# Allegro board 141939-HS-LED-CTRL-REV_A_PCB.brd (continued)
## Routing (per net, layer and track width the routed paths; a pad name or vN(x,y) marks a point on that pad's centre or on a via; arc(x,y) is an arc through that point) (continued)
SD_A11: length 34.6
  TOP w0.152: P1.P8 v1(84.91,34.66)
  BOTTOM w0.152: U5.35 106.33,48.33 104.27,50.39 93.6,50.39 88.4,45.18 88.4,44.42 84.91,40.93 v1(84.91,34.66)
SD_BA0: length 30.9
  TOP w0.152: P1.K2 v1(90.91,30.66)
  BOTTOM w0.152: v1(90.91,30.66) 91.15,30.66 91.65,31.16 93.81,31.16 94.16,31.52 94.42,31.52 95.29,30.64 95.54,30.64 95.72,30.82 95.72,31.08 94.85,31.95 94.85,32.2 95.03,32.38 95.28,32.38 96.15,31.51 96.4,31.51 96.58,31.69 96.58,31.94 95.82,32.7 95.82,33.21 97.3,34.69 98.06,34.69 98.24,34.86 98.24,35.12 97.73,35.63 97.73,35.88 97.91,36.06 98.16,36.06 98.67,35.55 98.92,35.55 99.1,35.73 99.1,35.98 98.48,36.6 98.48,36.85 100.62,38.99 105.33,38.99 105.54,38.79 105.54,37.54 105.74,37.34 106.24,37.34 106.33,37.25 U5.20
SD_BA1: length 30.6
  TOP w0.152: P1.K1 v1(91.91,30.66)
  BOTTOM w0.152: v1(91.91,30.66) 94.16,30.66 94.36,30.46 94.36,30.43 94.56,30.23 95.63,30.23 97.03,31.62 97.03,32.13 96.27,32.89 96.27,33.15 96.43,33.31 96.68,33.31 97.57,32.42 97.83,32.42 98,32.6 98,32.85 97.11,33.74 97.11,34 97.29,34.17 97.55,34.17 98.37,33.35 98.62,33.35 98.8,33.53 98.8,33.78 98.44,34.14 98.44,34.43 99.46,35.45 99.75,35.45 99.79,35.4 100.05,35.4 100.22,35.58 100.22,35.83 99.71,36.34 99.71,36.6 100.33,37.21 100.33,38.15 100.53,38.35 101.4,38.35 101.6,38.15 101.6,37.39 101.78,37.21 102.04,37.21 102.21,37.39 102.21,38.27 102.55,38.61 105,38.61 105.16,38.45 105.16,37.38 105.53,37 U5.21
SD_CAS: length 32.1
  TOP w0.152: P1.F2 90.91,25.66 93.77,25.66 94.49,26.39 94.49,28.15 95.68,29.34 97.97,29.34 98.18,29.54 v1(98.18,29.69)
  BOTTOM w0.152: U5.17 108.73,33.99 108.53,33.78 107.47,33.78 107.27,33.99 107.27,34.75 107.09,34.92 106.84,34.92 106.66,34.75 106.66,33.96 106.48,33.78 103.84,33.78 103.64,33.58 103.64,29.82 103.5,29.69 100.29,29.69 100.11,29.51 100.11,28.25 99.93,28.07 99.68,28.07 99.5,28.25 99.5,29.51 99.32,29.69 v1(98.18,29.69)
SD_CKE: length 32.8
  TOP w0.152: P1.M6 v1(86.91,32.66)
  BOTTOM w0.152: U5.37 107.93,45.83 107.18,45.08 93.5,45.08 92.79,44.37 92.79,41.36 89.53,38.1 89.53,35.15 89.41,35.03 89.41,34.87 89.41,34.87 89.41,34.51 89.41,34.51 89.41,34.46 89.12,34.16 89.06,34.16 89.06,34.16 88.7,34.16 88.41,33.87 88.41,33.51 88.41,33.51 88.41,33.46 88.12,33.16 87.41,33.16 v1(86.91,32.66)
SD_CLK: length 30.3
  TOP w0.152: P1.T4 88.41,37.74 v4(89.03,38.35) 93.35,42.68 v1(93.35,44.04)
  BOTTOM w0.152: U5.38 108.73,46.15 108.91,45.97 109.93,45.97 110.11,45.79 110.11,45.54 109.93,45.36 108.91,45.36 108.73,45.18 108.73,45.11 108.35,44.72 94.03,44.72 v1(93.35,44.04)
SD_CS: length 30.3
  TOP w0.152: P1.L1 v1(91.91,31.66)
  BOTTOM w0.152: U5.19 107.13,37.03 107.3,37.2 107.41,37.2 107.57,37.36 107.57,37.59 107.41,37.75 106.1,37.75 105.92,37.92 105.92,38.18 106.1,38.35 107.26,38.35 107.44,38.53 107.44,38.79 107.26,38.96 105.99,38.96 105.59,39.37 100.36,39.37 97.06,36.06 97.06,35.81 97.36,35.51 97.36,35.26 97.18,35.08 96.93,35.08 96.63,35.38 96.37,35.38 96.19,35.2 96.19,34.95 96.5,34.65 96.5,34.39 96.32,34.21 96.06,34.21 95.76,34.52 95.51,34.52 95.25,34.26 95.25,34.02 95.26,34.02 95.59,33.7 95.59,33.48 95.39,33.29 95.14,33.29 94.95,33.48 94.7,33.48 94.52,33.3 94.52,33.05 94.71,32.86 94.71,32.61 94.53,32.43 94.28,32.43 94.09,32.62 93.83,32.62 93.65,32.44 93.65,32.19 93.85,32 93.85,31.74 93.77,31.66 v1(91.91,31.66)
SD_D0: length 43.4
  TOP w0.152: P1.P3 v1(89.91,34.66)
  BOTTOM w0.152: U5.2 120.73,40.56 117,44.29 109.19,44.29 108.33,43.43 95.54,43.43 89.91,37.81 v1(89.91,34.66)
SD_D1: length 41.9
  TOP w0.152: P1.N3 v1(89.91,33.66)
  BOTTOM w0.152: v1(89.91,33.66) 89.91,33.92 90.41,34.42 90.41,36.43 v3(90.55,36.58) 90.55,37.68 95.92,43.05 110.14,43.05 110.79,43.7 116.07,43.7 119.13,40.64 U5.4
SD_D2: length 41.4
  TOP w0.152: P1.P2 v1(90.91,34.66)
  BOTTOM w0.152: v1(90.91,34.66) 90.91,34.74 93.6,37.43 93.6,38.86 93.09,39.37 93.09,39.62 93.49,40.02 93.74,40.02 93.93,39.83 94.18,39.83 94.36,40.01 94.36,40.26 94.17,40.45 94.17,40.7 94.35,40.88 94.6,40.88 94.79,40.69 95.05,40.69 95.22,40.87 95.22,41.12 95.03,41.31 95.03,41.57 95.21,41.74 95.46,41.74 95.66,41.55 95.91,41.55 96.09,41.73 96.09,41.98 95.89,42.18 95.89,42.43 96.04,42.57 116.43,42.57 118.33,40.67 U5.5
SD_D3: length 42.4
  TOP w0.152: P1.L6 v1(86.91,31.66)
  BOTTOM w0.152: v1(86.91,31.66) 88.27,31.66 88.41,31.81 88.41,32.87 88.7,33.16 90.12,33.16 90.41,33.46 90.41,33.87 90.7,34.16 91.12,34.16 91.57,34.62 91.57,34.77 93.98,37.18 93.98,39.12 97.08,42.21 115.52,42.21 116.73,41 U5.7
SD_D4: length 41.2
  TOP w0.152: P1.N2 v1(90.91,33.66)
  BOTTOM w0.152: U5.8 115.93,41.17 115.24,41.86 97.23,41.86 96.78,41.41 96.78,41.16 97.29,40.65 97.29,40.4 97.12,40.22 96.86,40.22 96.35,40.73 96.1,40.73 95.92,40.55 95.92,40.3 96.43,39.79 96.43,39.54 96.25,39.36 96,39.36 95.49,39.87 95.24,39.87 95.06,39.69 95.06,39.44 95.57,38.93 95.57,38.67 95.39,38.49 95.14,38.49 94.63,39 94.49,39 94.36,38.88 94.36,37.94 94.72,37.58 94.72,37.28 91.1,33.66 v1(90.91,33.66)
SD_D5: length 41.4
  TOP w0.152: P1.L4 v1(88.91,31.66)
  BOTTOM w0.152: v1(88.91,31.66) 89.41,32.16 90.19,32.16 92.22,34.2 92.22,34.27 95.12,37.18 95.12,37.72 98.04,40.64 98.04,40.77 97.79,41.02 97.79,41.38 97.92,41.5 112.7,41.5 112.88,41.33 112.88,40.82 113.06,40.64 113.31,40.64 113.49,40.82 113.49,41.33 113.67,41.5 113.92,41.5 114.1,41.33 114.1,40.82 114.28,40.64 114.53,40.64 114.71,40.82 114.71,41.33 114.89,41.5 115.09,41.5 115.57,41.02 115.57,37.34 115.44,37.21 114.55,37.21 114.33,36.99 U5.10
SD_D6: length 42.2
  TOP w0.152: P1.L3 v1(89.91,31.66)
  BOTTOM w0.152: v1(89.91,31.66) 90.12,31.66 91.45,32.99 91.7,32.99 91.88,32.82 92.13,32.82 92.31,33 92.31,33.25 92.13,33.43 92.13,33.68 95.58,37.13 95.58,37.67 99.06,41.15 110.26,41.15 110.62,40.79 110.62,40.46 110.82,40.26 111.61,40.26 111.82,40.46 111.82,40.97 112,41.15 112.25,41.15 112.43,40.97 112.43,40.44 112.61,40.26 115.04,40.26 115.19,40.11 115.19,39.9 115.04,39.75 114.23,39.75 114.05,39.57 114.05,39.3 114.23,39.12 115.04,39.12 115.19,38.97 115.19,38.76 115.04,38.61 114.19,38.61 114.05,38.46 114.05,38.25 114.19,38.1 115.04,38.1 115.19,37.95 115.19,37.74 115.04,37.59 114.17,37.59 113.98,37.4 113.98,37.15 113.92,37.08 113.67,37.08 113.53,36.95 U5.11
SD_D7: length 41.3
  TOP w0.152: P1.N1 91.91,33.66 v1(92.91,33.66)
  BOTTOM w0.152: U5.13 111.93,37.01 112.14,37.21 113.26,37.21 113.41,37.36 113.41,37.57 113.26,37.72 111.53,37.72 111.38,37.87 111.38,38.08 111.53,38.23 113.52,38.23 113.67,38.38 113.67,38.59 113.52,38.73 111.42,38.73 111.25,38.91 111.25,39.15 111.42,39.32 113.5,39.32 113.67,39.48 113.67,39.71 113.5,39.88 110.44,39.88 110.24,40.08 110.24,40.61 110.08,40.77 109.87,40.77 109.72,40.61 109.72,40.02 109.57,39.88 109.37,39.88 109.22,40.02 109.22,40.41 108.86,40.77 99.19,40.77 96.01,37.59 96.01,37.05 92.91,33.95 v1(92.91,33.66)
SD_D8: length 67.9
  TOP w0.152: P1.M8 v1(84.91,32.66)
  BOTTOM w0.152: v1(84.91,32.66) 84.91,32.67 84.08,33.5 84.08,41.75 84.71,42.39 84.71,49.03 85.37,49.68 85.62,49.68 86.19,49.11 86.45,49.11 86.62,49.29 86.62,49.54 86.05,50.11 86.05,50.36 86.23,50.54 86.48,50.54 87.06,49.97 87.31,49.97 87.49,50.15 87.49,50.4 86.91,50.97 86.91,51.23 87.35,51.66 108.71,51.66 108.89,51.84 108.89,53.54 109.07,53.72 109.32,53.72 109.5,53.54 109.5,52.38 109.68,52.2 109.93,52.2 110.11,52.38 110.11,53.54 110.29,53.72 111.18,53.72 111.38,53.52 111.38,53.16 111.2,52.98 110.67,52.98 110.49,52.8 110.49,52.55 110.67,52.37 111.2,52.37 111.38,52.19 111.38,51.94 111.2,51.76 110.16,51.76 109.98,51.58 109.98,51.33 110.16,51.15 111.96,51.15 112.14,50.97 112.14,50.72 111.96,50.54 110.16,50.54 109.98,50.36 109.98,50.11 110.16,49.93 111.2,49.93 111.38,49.75 111.38,49.25 111.93,48.7 U5.42
SD_D9: length 68.3
  TOP w0.152: P1.L8 v1(84.91,31.66)
  BOTTOM w0.152: U5.44 113.53,48.22 114.18,48.86 114.18,49.84 111.89,52.13 111.89,53.9 111.68,54.1 108.7,54.1 108.52,53.92 108.52,52.38 108.34,52.2 108.09,52.2 107.91,52.38 107.91,53.92 107.73,54.1 107.48,54.1 107.3,53.92 107.3,52.38 107.12,52.2 106.87,52.2 106.69,52.38 106.69,53.92 106.51,54.1 106.26,54.1 106.08,53.92 106.08,52.38 105.9,52.2 105.65,52.2 105.47,52.38 105.47,54.06 105.31,54.23 105.07,54.23 104.9,54.06 104.9,52.24 104.7,52.04 86.84,52.04 83.42,48.62 83.42,36.19 83.77,35.83 83.77,32.8 v1(84.91,31.66)
SD_D10: length 67.6
  TOP w0.152: P1.L9 83.41,31.16 v1(82.91,31.66)
  BOTTOM w0.152: v1(82.91,31.66) 83.44,32.2 83.44,35.53 83.06,35.91 83.06,49.03 86.46,52.42 104.11,52.42 104.52,52.83 104.52,54.23 104.9,54.61 108.38,54.61 108.58,54.81 108.58,56.31 108.79,56.52 109.02,56.52 109.22,56.31 109.22,54.81 109.42,54.61 109.65,54.61 109.86,54.81 109.86,56.31 110.06,56.52 110.29,56.52 110.49,56.31 110.49,54.64 110.65,54.48 110.88,54.48 111.04,54.64 111.04,55.45 111.22,55.63 111.47,55.63 111.65,55.45 111.65,54.79 111.83,54.61 112.06,54.61 112.27,54.41 112.27,52.55 114.56,50.26 114.56,48.48 114.33,48.26 U5.45
SD_D11: length 68.1
  TOP w0.152: P1.N9 83.41,33.16 v1(82.91,33.66)
  BOTTOM w0.152: v1(82.91,33.66) 82.91,35.3 82.68,35.53 82.68,49.53 85.95,52.8 103.81,52.8 104.01,53 104.01,54.79 104.22,54.99 105.46,54.99 105.66,55.19 105.66,56.69 105.87,56.9 106.1,56.9 106.3,56.69 106.3,55.19 106.5,54.99 106.73,54.99 106.93,55.19 106.93,56.69 107.14,56.9 107.37,56.9 107.57,56.69 107.57,55.19 107.77,54.99 108,54.99 108.2,55.19 108.2,56.69 108.41,56.9 110.74,56.9 112.78,54.86 112.78,52.81 115.19,50.39 115.19,49.22 115.93,48.48 U5.47
SD_D12: length 68.1
  TOP w0.152: v1(82.91,32.66) 83.41,32.16 P1.M9
  BOTTOM w0.152: v1(82.91,32.66) 82.41,33.16 82.41,35.17 82.3,35.28 82.3,53.18 84.59,55.47 103.81,55.47 104.01,55.67 104.01,57.07 104.22,57.28 104.44,57.28 104.65,57.07 104.65,55.67 104.85,55.47 105.08,55.47 105.28,55.67 105.28,57.07 105.49,57.28 110.87,57.28 115.83,52.32 115.83,49.19 116.73,48.29 U5.48
SD_D13: length 69.4
  TOP w0.152: v1(81.91,31.66) 82.41,31.16 P1.L10
  BOTTOM w0.152: U5.50 118.33,50.42 110.89,57.86 84.66,57.86 81.06,54.26 81.06,43.3 80.14,42.39 80.14,37.56 81.16,36.55 81.16,35.15 81.41,34.9 81.41,32.16 v1(81.91,31.66)
SD_D14: length 67.9
  TOP w0.152: v1(80.91,34.66) 81.41,34.16 P1.P11
  BOTTOM w0.152: v1(80.91,34.66) 80.78,34.8 80.78,36.16 79.63,37.31 79.63,43.02 80.4,43.79 80.4,54.33 84.37,58.29 111.23,58.29 119.13,50.39 U5.51
SD_D15: length 68.1
  TOP w0.152: P1.T14 78.41,36.16 v1(77.91,36.66)
  BOTTOM w0.152: U5.53 120.73,49.42 111.48,58.67 83.63,58.67 79.93,54.97 79.93,43.99 77.98,42.04 77.98,36.74 v1(77.91,36.66)
SD_DQ0: length 41.3
  TOP w0.152: P1.L2 v1(90.91,31.66)
  BOTTOM w0.152: U5.15 110.33,36.98 110.54,37.19 111.13,37.19 111.25,37.3 111.25,37.47 111.13,37.59 109.59,37.59 109.47,37.7 109.47,37.86 109.59,37.97 110.85,37.97 111,38.12 111,38.33 110.85,38.48 108.48,38.48 108.33,38.63 108.33,38.84 108.48,38.99 110.72,38.99 110.87,39.14 110.87,39.35 110.72,39.5 109.04,39.5 108.84,39.7 108.84,40.03 108.64,40.23 107.72,40.23 107.55,40.05 107.55,39.93 107.37,39.75 107.11,39.75 106.94,39.93 106.94,40.18 106.73,40.39 100.13,40.39 99.86,40.11 99.68,40.11 99.59,40.2 99.33,40.2 99.15,40.02 99.15,39.77 99.24,39.68 99.24,39.43 99.07,39.25 98.81,39.25 98.62,39.44 98.37,39.44 98.19,39.26 98.19,39.01 98.38,38.82 98.38,38.56 98.2,38.39 97.95,38.39 97.76,38.58 97.51,38.58 97.33,38.4 97.33,38.15 97.52,37.95 97.52,37.7 97.34,37.52 97.09,37.52 96.9,37.72 96.64,37.72 96.46,37.54 96.46,37.39 96.65,37.21 96.65,37.08 94.29,34.73 94.29,34.48 94.36,34.41 94.36,34.16 94.18,33.98 93.93,33.98 93.86,34.05 93.64,34.05 93.5,33.91 93.5,33.66 93.6,33.56 93.6,33.49 92.62,32.51 91.6,32.51 90.91,31.82 v1(90.91,31.66)
SD_DQ1: length 68.9
  TOP w0.152: P1.N8 v1(84.91,33.66)
  BOTTOM w0.152: U5.39 109.53,50.95 109.33,51.15 109,51.15 108.82,50.97 108.82,49.71 108.64,49.53 108.39,49.53 108.21,49.71 108.21,50.97 108.03,51.15 107.78,51.15 107.6,50.97 107.6,49.71 107.42,49.53 107.17,49.53 106.99,49.71 106.99,50.97 106.81,51.15 106.56,51.15 106.38,50.97 106.38,49.71 106.2,49.53 105.95,49.53 105.77,49.71 105.77,50.97 105.59,51.15 91.83,51.15 91.66,50.97 91.66,49.07 91.48,48.9 91.22,48.9 91.05,49.07 91.05,50.97 90.87,51.15 90.61,51.15 90.44,50.97 90.44,48.31 90.26,48.13 90.01,48.13 89.83,48.31 89.83,50.97 89.65,51.15 89.4,51.15 89.22,50.97 89.22,48.31 89.04,48.13 88.79,48.13 88.61,48.31 88.61,50.97 88.43,51.15 88.09,51.15 87.88,50.95 87.88,47.97 87.71,47.8 87.68,47.8 86.74,46.86 86.74,43.4 84.46,41.12 84.46,34.92 84.41,34.87 84.41,34.16 v1(84.91,33.66)
SD_RAS: length 30.3
  TOP w0.152: P1.K5 v1(87.91,30.66)
  BOTTOM w0.152: U5.18 107.93,37.29 108.14,37.5 108.91,37.5 109.09,37.67 109.09,37.93 108.91,38.1 108.11,38.1 107.93,38.28 107.93,39.01 107.57,39.37 106.17,39.37 105.79,39.75 100.08,39.75 94.87,34.54 94.87,34.16 92.87,32.16 91.7,32.16 91.41,31.87 91.41,31.56 91.41,31.46 91.12,31.16 88.11,31.16 87.91,30.96 v1(87.91,30.66)
SD_WE: length 31.4
  TOP w0.152: P1.D1 93.14,24.16 93.32,23.98 93.32,23.17 93.49,22.99 93.75,22.99 93.93,23.17 93.93,23.98 94.1,24.16 94.33,24.16 94.49,24 94.49,23.24 94.61,23.11 94.77,23.11 95.12,23.46 98.94,23.46 100.08,24.61 100.08,28.42 v1(100.72,29.05)
  BOTTOM w0.152: U5.16 109.53,34.67 109.28,34.42 109.28,33.97 108.71,33.4 105.06,33.4 104.02,32.36 104.02,29.31 103.76,29.05 v1(100.72,29.05)
SWCLK: length 19.8
  TOP w0.152: U26.76 119.1,15.69 120.97,17.56 120.97,20.48 122.56,22.07 122.56,28.67 122.94,29.05 R129.2 123.35,29.02 J3.2
SWDIO: length 25.9
  TOP w0.152: v1(119,16.48) 120.53,18 120.53,20.8 122.18,22.45 122.18,30.07 122.81,30.7 R130.1 125.48,30.7 J3.3 ; U26.72 v1(113.85,15.26)
  BOTTOM w0.152: v1(113.85,15.26) 115.07,16.48 v1(119,16.48)
TCK: length 46.7
  TOP w0.152: P1.H3 v1(89.91,28.66)
  BOTTOM w0.152: v1(89.91,28.66) 92.33,28.66 92.58,28.41 92.58,25.88 95.13,23.34 101.44,23.34 104.65,26.54 109.73,26.54 110.39,25.88 121.67,25.88 R11.2 122.31,24.86 122.56,24.61 123.19,24.61 123.83,23.97 123.83,21.94 123.39,21.5 U6.1 122.71,20.4 J1.1
TDI: length 54.9
  TOP w0.152: v1(92.08,27.66) 88.92,27.66 P1.H4
  BOTTOM w0.152: J1.9 120.65,14.46 120.65,22.07 121.99,23.4 U6.3 122.71,23.95 122.56,24.1 122.31,24.1 121.29,25.12 110.27,25.12 109.22,26.16 104.78,26.16 101.57,22.96 94.75,22.96 92.08,25.62 v1(92.08,27.66)
TDO: length 53.9
  TOP w0.152: P1.J4 v1(88.91,28.66)
  BOTTOM w0.152: J1.3 123.67,17.46 124.62,18.41 124.62,20.08 125.21,20.67 U6.6 124.4,21.5 124.21,21.69 124.21,25.24 123.96,25.5 123.96,27.15 122.18,28.93 111.26,28.93 109.38,27.05 104.65,27.05 101.32,23.72 95.51,23.72 92.96,26.26 92.96,28.55 92.21,29.31 89.79,29.31 89.15,28.66 v1(88.91,28.66)
TF_CLK: length 32.7
  TOP w0.152: U26.80 118.05,17.69 118.37,18 118.37,21.31 120.4,23.34 120.4,29.18 117.48,32.1 117.48,35.02 115.32,37.18 115.32,40.36 113.64,42.04 J4.5 111.29,42.04 111.13,41.88 R163.2
TF_CMD: length 39.6
  TOP w0.152: U26.83 115.36,19.19 v1(115.19,19.02) ; R162.2 R139.2 110.19,44.24 J4.3 113.85,44.24 116.08,42.01 116.08,37.05 117.86,35.28 117.86,32.43 120.86,29.43 120.86,23.16 119,21.31 v1(119,19.02)
  BOTTOM w0.152: v1(115.19,19.02) v1(119,19.02)
TF_DATA0: length 39.2
  TOP w0.152: v1(118.75,22.58) 119.89,23.72 119.89,29.05 116.97,31.97 116.97,34.89 114.81,37.05 114.81,38.58 113.55,39.84 J4.7 111.38,39.84 111.13,39.59 R138.2 R158.2 ; U26.65 110.35,15.65 111.68,16.98 v1(114.18,16.98)
  BOTTOM w0.152: v1(114.18,16.98) 114.18,19.02 117.73,22.58 v1(118.75,22.58)
TF_DATA1: length 36.5
  TOP w0.152: U26.66 110.85,14.93 112.02,16.1 v1(113.16,16.1) ; R159.2 R137.2 110.4,38.74 J4.8 113.51,38.74 114.05,38.2 114.05,37.18 116.46,34.77 116.46,31.85 119.51,28.8 119.51,24.61 v1(118.75,23.85)
  BOTTOM w0.152: v1(118.75,23.85) 118.24,23.85 113.16,18.77 v1(113.16,16.1)
TF_DATA2: length 40.9
  TOP w0.152: R160.2 R141.2 111.27,46.44 J4.1 113.68,46.44 119,41.12 119,32.61 121.67,29.94 121.67,22.58 120.12,21.02 120.12,18.48 118.32,16.69 U26.78
TF_DATA3: length 38.4
  TOP w0.152: U26.79 118.19,17.19 119.72,18.72 119.72,21.39 121.29,22.96 121.29,29.69 118.24,32.74 118.24,40.74 113.64,45.34 J4.2 111.03,45.34 111,45.31 R161.2 R140.2
TMS: length 59.2
  TOP w0.152: P1.J5 v1(87.91,29.66)
  BOTTOM w0.152: J1.5 123.65,15.54 124.59,16.48 126.37,16.48 127,17.11 127,22.83 126.44,23.4 U6.4 125.21,24.88 R12.1 124.46,25.62 124.46,28.16 123.32,29.31 110.88,29.31 109.99,28.42 101.73,28.42 99.45,26.13 94.26,26.13 93.73,26.67 93.73,29.08 92.65,30.16 88.41,30.16 v1(87.91,29.66)
USART_RX: length 32.4
  TOP w0.152: U26.26 103.3,27.69 104.27,26.72 104.27,25.65 v1(104.78,25.15)
  BOTTOM w0.152: J7.2 113.45,5.8 110.88,8.38 110.88,15.59 107.7,18.77 107.7,22.6 106.05,24.26 106.05,24.89 105.79,25.15 v1(104.78,25.15)
USART_TO_FPGA_RX: length 43.6
  TOP w0.152: P1.A13 79.41,16.96 84.71,11.65 91.44,11.65 94.75,8.35 107.7,8.35 112.35,13 U26.69
USART_TO_FPGA_TX: length 43.2
  TOP w0.152: P1.B13 79.89,21.68 79.89,19.57 79.89,19.56 79.89,17.12 84.97,12.03 92.21,12.03 95.39,8.85 107.62,8.85 111.85,13.08 U26.68
USART_TX: length 31
  TOP w0.152: v1(105.41,24.48) 105.41,26.59 103.35,28.65 U26.25
  BOTTOM w0.152: v1(105.41,24.48) 105.41,24.1 107.06,22.45 107.06,18.76 109.59,16.23 109.59,7.88 111.45,6.03 J7.1
WR: length 34.2
  TOP w0.152: v1(105.41,19.65) 113.14,19.65 114.18,20.69 U26.86 ; P1.C6 v1(86.91,22.66)
  BOTTOM w0.152: v1(105.41,19.65) 104.86,19.1 103.71,19.1 103.51,18.89 88.9,18.89 86.91,20.89 v1(86.91,22.66)
N00507: length 2.6
  TOP w0.381: U1.7 22.1,49.41 21.21,48.52 R1.1
N00656: length 2.5
  TOP w0.381: U1.8 21.75,48.14 21.12,47.5 C2.1
N00761: length 1
  TOP w0.381: R2.1 C3.2
N00851: length 2.2
  TOP w0.381: U1.6 C3.1
N00855: length 0.7
  TOP w0.381: C4.1 31.28,47.25
N00885: length 3.2
  TOP w0.381: C4.2 30.26,47.31 29.44,48.14 U1.1
N00957: length 5
  TOP w0.381: R4.2 R3.2 24.64,52.55 24.04,51.95 U1.5
N59239: length 3.1
  TOP w0.152: U8.2 48.05,41.16 48.21,41.33
  TOP w0.381: L6.2 49.02,41.84 48.76,41.58 48.47,41.58 48.21,41.33
N59407: length 6.4
  TOP w0.152: Y1.3 45.25,44.5 45.25,44.04 C41.2 46.01,42.51 46.65,42.51 46.84,42.31 U8.5
N59411: length 8.3
  TOP w0.152: Y1.1 45.97,46.92 45.63,46.58 45.63,44.17 C39.2 46.14,43.15 46.39,42.9 46.9,42.9 47.25,42.55 U8.4
N59605: length 4
  TOP w0.152: 48.21,23.8 48.05,23.63 U9.2
  TOP w0.381: 48.21,23.8 48.64,24.23 49.44,24.23 49.91,24.7 L7.2
N59753: length 5.2
  TOP w0.152: Y2.3 46.14,26.47 46.14,26 C42.2 46.39,24.99 46.52,24.99 46.84,24.66 U9.5
N59757: length 7.1
  TOP w0.152: Y2.1 46.86,28.89 46.52,28.54 46.52,26.13 C40.2 47.25,25.4 U9.4
N68560: length 2.3
  TOP w0.381: U23.1 v1(35.34,17.88)
  BOTTOM w0.381: C226.2 v1(35.34,17.88)
N68564: length 2.4
  TOP w0.381: U23.48 v1(21.12,17.88)
  BOTTOM w0.381: R111.1 v1(21.12,17.88)
N68628: length 2.3
  TOP w0.381: U23.4 v1(35.34,20.92)
  BOTTOM w0.381: C227.2 v1(35.34,20.92)
N68632: length 2.4
  TOP w0.381: U23.45 v1(21.12,20.92)
  BOTTOM w0.381: R112.1 v1(21.12,20.92)
N68696: length 2.3
  TOP w0.381: U23.7 v1(35.34,23.97)
  BOTTOM w0.381: v1(35.34,23.97) C228.2
N68700: length 2.4
  TOP w0.381: U23.42 v1(21.12,23.97)
  BOTTOM w0.381: R113.1 v1(21.12,23.97)
N68748: length 2.3
  TOP w0.381: U23.10 v1(35.34,27.02)
  BOTTOM w0.381: C229.2 v1(35.34,27.02)
N68752: length 2.4
  TOP w0.381: U23.39 v1(21.12,27.02)
  BOTTOM w0.381: R114.1 v1(21.12,27.02)
N68848: length 2.3
  TOP w0.381: U23.13 v1(35.34,30.07)
  BOTTOM w0.381: C230.2 v1(35.34,30.07)
N68852: length 2.4
  TOP w0.381: U23.36 v1(21.12,30.07)
  BOTTOM w0.381: R115.1 v1(21.12,30.07)
N68966: length 2.3
  TOP w0.381: U23.16 v1(35.34,33.12)
  BOTTOM w0.381: C231.2 v1(35.34,33.12)
N68970: length 2.4
  TOP w0.381: U23.33 v1(21.12,33.12)
  BOTTOM w0.381: R116.1 v1(21.12,33.12)
N69086: length 2.3
  TOP w0.381: U23.19 v1(35.34,36.16)
  BOTTOM w0.381: C232.2 v1(35.34,36.16)
N69090: length 2.4
  TOP w0.381: U23.30 v1(21.12,36.16)
  BOTTOM w0.381: R117.1 v1(21.12,36.16)
N69194: length 2.3
  TOP w0.381: U23.22 v1(35.34,39.21)
  BOTTOM w0.381: C233.2 v1(35.34,39.21)
N69198: length 2.4
  TOP w0.381: U23.27 v1(21.12,39.21)
  BOTTOM w0.381: R118.1 v1(21.12,39.21)
N70343: length 9.5
  TOP w0.152: v1(78.91,28.66) 79.91,28.66 P1.H12
  BOTTOM w0.152: v1(78.91,28.66) 78.49,29.08 74.55,29.08 74.04,28.57 72.39,28.57 R164.1
N5916714: length 5.7
  TOP w0.152: U8.7 46.05,41.51 45.76,41.8 45.76,42.13 45.38,42.51 44.87,42.51 44.71,42.36 43.88,42.36 R31.1
N5956514: length 5.8
  TOP w0.152: U9.7 46.05,23.99 45.76,24.28 45.76,24.61 45.38,24.99 43.72,24.99 43.09,25.62 R33.1
N15733620: length 21.9
  TOP w0.152: R127.2 v1(116.08,11.91) ; U26.16 107.85,24.58 v1(107.95,24.48)
  BOTTOM w0.152: v1(107.95,24.48) 108.97,23.46 108.97,19.02 v1(116.08,11.91)
N15733628: length 21.9
  TOP w0.152: R128.2 v1(114.43,11.91) ; U26.17 107.35,25.15 v1(106.68,24.48)
  BOTTOM w0.152: v1(114.43,11.91) 114.43,12.8 108.34,18.89 108.34,22.83 v1(106.68,24.48)
N15733972: length 3.7
  TOP w0.152: U26.94 118.19,24.69 118.88,25.37 R131.2
N15734280: length 9.2
  TOP w0.229: v1(104.65,31.85) 105.21,31.29 105.21,30.72 105.35,30.58 U26.21 ; v1(104.65,30.7) 104.85,30.5 U26.22
  BOTTOM w0.381: L10.1 107.61,32.74 C251.2 C252.2 105.16,32.74 104.65,32.23 v1(104.65,31.85) v1(104.65,30.7)
N15734652: length 2.7
  TOP w0.152: R135.2 99.07,22.19 U26.37
N15801432: length 1.5
  BOTTOM w0.305: U25.4 C242.1
N15813450: length 1.3
  TOP w0.381: R142.1 D26.1
N15817579: length 2.3
  TOP w0.152: R13.2 U7.2
N15925802: length 1.4
  TOP w0.152: D37.1 15.24,47.6 R146.2
N15925882: length 1.4
  TOP w0.152: D36.1 12.2,47.6 R147.2
N15925976: length 1.4
  TOP w0.152: R148.2 12.2,11.16 D35.1
N15926055: length 1.4
  TOP w0.152: D34.1 15.63,12.53 R149.2
N15994943: length 3.5
  BOTTOM w0.381: R114.2 23.91,27.02 ; R113.2 23.91,23.97 ; R112.2 23.91,20.92 ; R111.2 23.91,17.88
N15995237: length 3.5
  BOTTOM w0.381: R115.2 23.91,30.07 ; R116.2 23.91,33.12 ; 23.91,36.16 R117.2 ; 23.91,39.21 R118.2
N16105743: length 22.2
  TOP w0.152: v1(96.77,13.84) 97.16,13.46 R165.1 ; P1.E8 v1(84.91,24.66)
  BOTTOM w0.152: v1(84.91,24.66) 84.86,24.66 84.33,24.13 84.33,22.61 85.34,21.59 85.34,19.56 87.76,17.14 94.87,17.14 96.77,15.24 v1(96.77,13.84)
N16105815: length 1.4
  TOP w0.152: D38.2 96.14,11.57 R165.2
N157335061: length 1.3
  TOP w0.152: R128.1 D1.2
N157335281: length 1.3
  TOP w0.152: R127.1 D2.2

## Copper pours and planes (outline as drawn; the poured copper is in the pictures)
A2V5 on BOTTOM: 81.54,30.35 81.54,29.18 81.92,28.8 85.98,28.8 86.24,29.05 86.24,30.45 86.75,30.96 87.25,30.96 87.38,30.83 87.38,30.2 87.44,30.13 87.44,27.85 87.51,27.78 87.51,26.51 88.02,26 88.02,25.62 87.76,25.37 87.63,25.37 87,26 81.67,26 81.16,25.5 79.63,25.5 79.51,25.62 79.52,25.64 78.14,27.02 77.6,27.02 77.22,26.64 71.76,26.64 68.58,23.46 68.58,13.05 70.49,11.15 76.97,11.15 78.24,9.88 78.24,5.05 81.16,2.13 107.95,2.13 108.21,1.87 108.21,1.11 107.95,0.86 80.01,0.86 76.59,4.29 76.59,9.37 75.82,10.13 72.78,10.13 72.39,10.51 69.22,10.51 67.7,12.03 67.7,24.1 69.6,26 69.6,30.07 69.85,30.32 70.87,30.32 71.12,30.07 71.12,28.8 71.51,28.42 74.17,28.42 74.55,28.8 79.51,28.8 80.27,29.56 80.27,30.36 80.64,30.73 81.16,30.73
D1V2 on TOP: 63.66,43.28 66.33,43.28 66.58,43.02 66.58,38.83 66.46,38.7 63.28,38.7 63.03,38.96 63.03,42.64
D1V2 on ART03: 82.55,26.51 84.97,26.51 87.51,23.97 88.02,23.97 88.65,23.34 88.9,23.34 89.03,23.46 89.03,25.37 87.25,27.15 87.25,31.37 87.76,31.88 88.17,31.88 88.79,32.49 89.16,32.86 89.16,33.88 89.03,34.01 85.63,34.01 85.09,34.54 85.09,40.01 83.44,41.66 64.26,41.66 63.75,41.15 63.75,40.61 63.76,40.61 63.76,38.07 64.27,37.56 75.82,37.56 75.89,37.5 79.57,37.5 80.14,38.07 81.28,38.07 81.54,37.82 81.54,35.78 80.4,35.78 79.63,35.02 79.63,29.31 80.78,28.16 80.78,24.99 79.63,23.85 79.63,23.34 79.76,23.21 80.52,23.21 82.43,25.12 82.43,26.39
D3V3 on TOP (solid shape): 38.36,57.25 38.36,54.2 37.98,53.82 31.5,53.82 31.25,54.07 31.25,57.37 31.37,57.5 38.1,57.5
D3V3 on BOTTOM (solid shape): 38.36,57.5 38.36,54.2 38.1,53.94 36.83,53.94 36.71,54.07 36.71,55.21 36.45,55.47 32.77,55.47 32.64,55.34 32.64,54.07 32.52,53.94 31.12,53.94 30.99,54.07 30.99,57.25 31.37,57.63 38.23,57.63
D3V3 on TOP: 55.28,46.07 59.09,46.07 59.47,45.69 59.47,44.42 59.22,44.17 55.28,44.17 55.03,44.42 55.03,45.82
D3V3 on BOTTOM: 66.93,30.58 67.19,30.32 68.46,30.32 68.58,30.2 68.58,29.56 68.46,29.43 64.01,29.43 63.89,29.56 63.89,30.45 64.01,30.58
D3V3 on ART03: 11.18,5.68 11.19,5.7 11.19,6.24 11.3,6.35 32.13,6.35 38.35,12.57 38.35,37.47 38.4,37.52 36.96,38.96 36.96,44.04 35.82,45.18 31.37,45.18 31.12,45.44 31.12,57.12 32.26,58.26 80.74,58.26 81.28,58.8 111.6,58.8 112.14,58.26 119.89,58.26 127.89,50.26 127.89,10.51 120.18,2.79 73.53,2.79 71.37,0.64 42.55,0.64 41.43,1.75 27.21,1.75 26.42,2.54 13.72,2.54 12.45,1.27 11.43,1.27 11.18,1.52 ; 1 cut-out
GND on TOP (solid shape): 123.83,7.34 123.83,5.18 123.7,5.05 117.99,5.05 117.86,5.18 117.86,7.46 117.99,7.59 123.58,7.59
GND on TOP (solid shape): 11.56,12.67 11.56,10.26 10.42,9.11 10.42,7.08 10.16,6.83 8.39,6.83 8.26,6.95 8.26,12.67 8.39,12.8 11.43,12.8
GND on TOP (solid shape): 123.32,55.21 123.32,54.71 123.83,54.2 123.83,53.06 123.7,52.93 121.42,52.93 121.16,52.67 117.99,52.67 117.86,52.8 117.86,55.34 117.99,55.47 123.07,55.47
GND on TOP (solid shape): 31.12,53.31 31.12,52.29 30.74,51.91 29.47,51.91 29.21,51.66 27.18,51.66 26.8,51.28 25.53,51.28 25.28,51.53 25.28,53.18 25.4,53.31 29.47,53.31 29.6,53.44 30.99,53.44
GND on TOP (solid shape): 11.82,58.58 11.82,56.61 13.85,54.58 13.85,50.52 13.59,50.26 11.82,50.26 11.56,50.01 11.56,48.36 11.31,48.1 8.64,48.1 8.39,48.36 8.39,58.77 8.58,58.96 11.43,58.96
GND on BOTTOM (solid shape): 31.12,53.31 32.77,53.31 32.9,53.18 36.58,53.18 36.83,53.44 40.14,53.44 40.26,53.31 40.26,51.4 39.88,51.02 25.28,51.02 24.9,51.4 22.86,51.4 22.1,52.17 22.1,55.09 22.36,55.34 29.09,55.34
GND on TOP: 48.45,36.29 48.42,36.27 44.87,36.27 44.84,36.29 44.84,39.85 44.87,39.87 48.42,39.87 48.45,39.85
GND on TOP: 60.23,38.7 60.11,38.83 60.11,41.5 59.85,41.75 59.85,43.28 59.73,43.4 58.33,43.4 58.08,43.15 58.08,41.5 57.69,41.12 56.3,41.12 54.9,42.51 54.9,43.78 55.03,43.91 55.66,43.91 56.17,43.4 57.31,43.4 57.82,43.91 62.01,43.91 62.14,43.78 62.14,43.4 62.01,43.28 60.62,43.28 60.49,43.15 60.49,42.26 60.74,42.01 62.27,42.01 62.39,41.88 62.39,38.83 62.27,38.7
GND on TOP: 48.45,18.77 48.42,18.74 44.87,18.74 44.84,18.77 44.84,22.32 44.87,22.35 48.42,22.35 48.45,22.32
GND on BOTTOM: 64.27,29.05 68.71,29.05 68.84,28.93 68.84,27.91 68.58,27.66 64.39,27.66 64.01,28.04 64.01,28.8
GND on BOTTOM: 68.48,31.06 68.58,30.96 68.58,30.68 68.55,30.64 67.25,30.64 66.55,31.34 64.14,31.34 64.01,31.47 64.01,33.12 64.27,33.37 67.31,33.37 67.44,33.24 67.44,31.14 67.52,31.06
GND on BOTTOM: 45.34,22.07 48.01,22.07 48.14,21.94 48.14,19.02 48.01,18.89 45.09,18.89 44.96,19.02 44.96,21.69
GND on BOTTOM: 48.01,39.59 48.14,39.47 48.14,36.55 48.01,36.42 45.09,36.42 44.96,36.55 44.96,39.21 45.34,39.59
GND on ART02: 9.65,47.24 24.64,47.24 28.7,43.18 34.04,43.18 34.54,42.67 34.54,15.37 32.51,13.34 7.88,13.34 6.61,12.06 6.61,0.99 6.83,0.76 26.83,0.76 27.05,0.99 129.04,0.99 129.04,58.9 8.51,58.9 8,58.39 8,48.9
GND_EARTH on TOP: 1.02,59.15 6.1,59.15 6.86,58.39 6.86,48.74 6.61,48.48 4.96,48.48 4.45,48.99 4.45,53.06 3.43,54.07 1.4,54.07 0.77,54.71 0.77,58.9
GND_EARTH on BOTTOM: 20.71,16.61 20.83,16.48 20.83,14.19 20.32,13.69 3.05,13.69 0.77,15.97 0.77,58.9 1.02,59.15 6.1,59.15 6.86,58.39 6.86,47.4 7.37,46.9 12.58,46.9 14.93,44.55 23.63,44.55 23.75,44.42 23.75,43.4 23.63,43.28 14.23,43.28 11.94,45.56 6.86,45.56 5.47,44.17 5.47,15.72 6.48,14.7 17.53,14.7 19.44,16.61
VCC_5V on TOP (solid shape): 27.18,50.01 28.96,50.01 29.09,49.88 29.09,48.99 28.96,48.86 24.52,48.86 24.39,48.99 24.39,50.39 24.52,50.52 26.67,50.52
VCC_5V on TOP (solid shape): 20.2,58.77 20.2,51.66 19.94,51.4 19.18,51.4 19.05,51.28 19.05,50.77 18.8,50.52 15.88,50.52 15.63,50.77 15.63,53.56 12.2,56.99 12.2,58.77 12.39,58.96 20.01,58.96
VCC_5V on BOTTOM: 27.06,48.36 26.8,48.1 18.55,48.1 18.17,48.48 18.17,53.69 18.42,53.94 21.21,53.94 21.72,53.44 21.72,51.91 22.99,50.64 26.93,50.64 27.06,50.52
VCC_5V on ART03: 10.93,6.45 11.18,6.7 31.25,6.7 37.6,13.05 37.6,37.82 36.45,38.96 36.45,44.04 35.56,44.93 30.1,44.93 27.56,47.47 27.56,49.75 26.8,50.52 24.64,50.52 24.39,50.26 24.39,47.59 28.71,43.28 34.04,43.28 34.55,42.77 34.55,14.7 29.85,10 9.02,10 8.13,9.11 8.13,1.77 8.64,1.27 10.67,1.27 10.93,1.53
Net_1 on BOTTOM (solid shape): outline of 388 points within 0.5,-6.5 129.5,-2.5
Net_2 on TOP (solid shape): outline of 388 points within 0.5,124.52 129.5,128.52
Net_3 on TOP (solid shape): outline of 388 points within 0.5,-6.5 129.5,-2.5
Net_4 on BOTTOM (solid shape): outline of 388 points within 0.5,124.52 129.5,128.52
N00855 on TOP (solid shape): 32.52,50.01 35.18,50.01 35.95,49.25 35.95,47.34 35.69,47.09 31.25,47.09 30.48,47.85 30.48,48.99 29.09,50.39 27.31,50.39 27.18,50.52 27.18,50.9 27.31,51.02 29.09,51.02 29.34,51.28 31.25,51.28
N15801228 on TOP: 66.2,45.69 66.46,45.44 66.46,44.29 66.2,44.04 62.65,44.04 62.39,44.29 60.87,44.29 60.74,44.42 60.74,45.44 61,45.69
N15962568 on TOP (solid shape): 6.74,11.65 6.74,1.24 6.23,0.73 1.27,0.73 0.77,1.24 0.77,8.89 1.14,9.27 3.81,9.27 4.57,10.03 4.57,11.78 4.7,11.91 6.48,11.91
N15964024 on TOP (solid shape): 129.29,5.43 129.29,1.11 128.91,0.73 124.28,0.73 124.11,0.87 123.9,0.92 118.88,0.92 118.88,3.4 119.13,3.65 124.21,3.65 126.12,5.56 129.16,5.56
N15964116 on TOP (solid shape): 129.29,58.9 129.29,54.83 128.78,54.33 126.12,54.33 123.58,56.87 118.88,56.87 118.75,56.99 118.75,59.08 123.9,59.08 124.12,59.13 124.29,59.28 128.91,59.28
N15994943 on BOTTOM: 23.66,27.27 23.79,27.4 24.29,27.4 24.42,27.27 24.42,14.96 24.29,14.83 22.52,14.83 22.39,14.96 22.39,16.73 22.64,16.99 23.53,16.99 23.66,17.11
N15995237 on BOTTOM: 23.66,29.81 23.66,40.36 23.53,40.48 22.39,40.48 22.13,40.74 22.13,41.5 22.39,41.75 24.29,41.75 24.42,41.63 24.42,29.81 24.29,29.69 23.79,29.69

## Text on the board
BOTTOM: HS-LED-CTRL-REV.A ARTWORK BOTTOM
Package Geometry/Pastemask Bottom: HS-LED-CTRL-REV.A PASTEMASK BOTTOM
Ref Des/Silkscreen Bottom: SD_D1 | ID4 | ID6 | HS-LED-CTRL-REV.A SILKSCREEN BOTTOM
User.Comments: HS-LED-CTRL-REV.A SOLDMASK TOP | HS-LED-CTRL-REV.A SOLDMASK BOTTOM | 60 | 55 | 7 | 8 | 30 | 4.5 | 40 | 120 | 115 | 2 | 11 | 4- | dia | 3.5 | 1.6
TOP: HS-LED-CTRL-REV.A ARTWORK TOP
Package Geometry/Pastemask Top: HS-LED-CTRL-REV.A PASTEMASK TOP
Ref Des/Silkscreen Top: SD_CLK | SD_A1 | G | V | HUB2 | HUB3 | HUB1 | HUB4 | T | R | JTAG | D | C | SWD | 5V | 3V3 | C-T | C-R | 485-RX | 485-RE | 458-DE | 485-TX | HS-LED-CTRL-REV.A | HS-LED-CTRL-REV.A SILKSCREEN TOP
ART02: HS-LED-CTRL-REV.A GROUND PLANE02
ART03: HS-LED-CTRL-REV.A POWER PLANE03
DIMENSION: HS-LED-CTRL-REV.A | HS-LED-CTRL-REV.A DRILL CHART | 1--Gerber TOP | 2--GROUND PLANE02 | 3--POWER PLANE03 | 4--Gerber BOTTOM | 60 | 2362.2 | 5118.1 | 130
COMPVAL_TYPE_TOP: FIGURE | SIZE | 8.0 | 10.0 | 32.0 | 36.0 | 44.0 | 64.0 | 106.0 | 40.0 | 80.0 | 130.0 | DRILL CHART: TOP to BOTTOM | ALL UNITS ARE IN MILS | PLATED | NON-PLATED | QTY | 13 | 534 | 27 | 19 | 64 | 3 | 4 | 60 | 2
